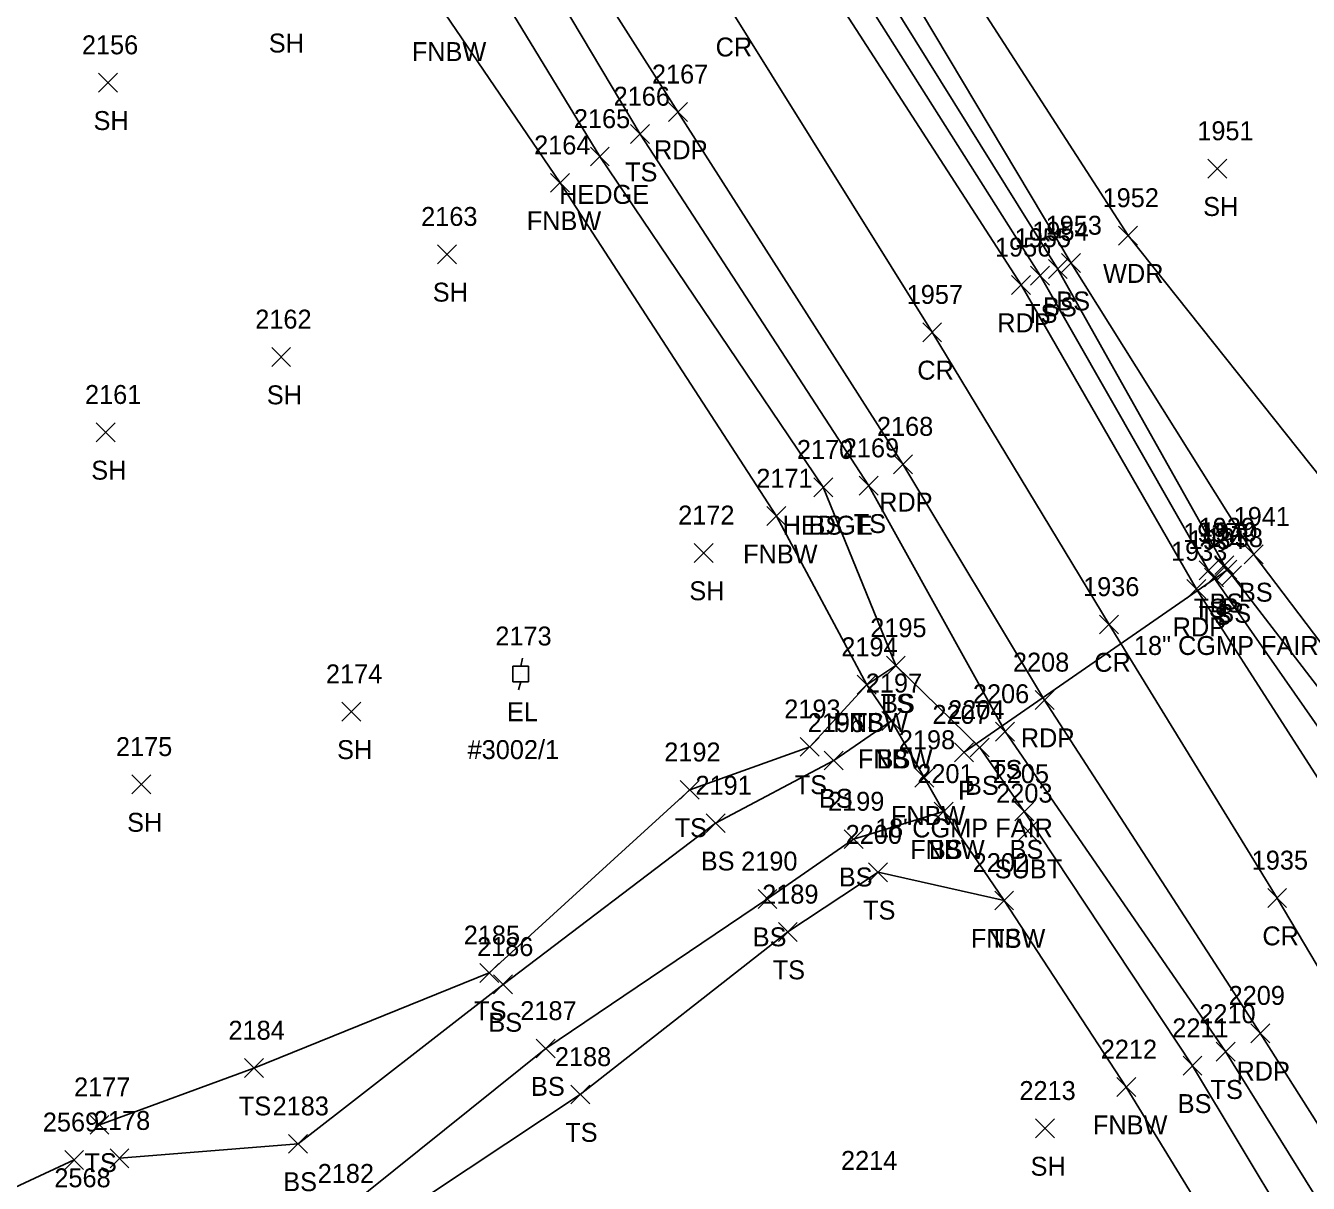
# Model space of a CAD drawing. Extents: x 1443590 to 1445966, y 578314 to 580556.
# Drawn here: x 1444914.1 to 1445049.7, y 579213.2 to 579335.5 of the extents above; entities that cross this region are included whole.
import ezdxf

# ---------------------------------------------------------------- set-up
doc = ezdxf.new("R2010")
doc.units = 0
for name, color, linetype in [('D_A', 7, 'Continuous'), ('D_C', 7, 'Continuous'), ('D_I', 7, 'Continuous'), ('D_TIC', 7, 'Continuous'), ('DCP', 7, 'Continuous'), ('L_A', 7, 'Continuous'), ('L_I', 7, 'Continuous'), ('L_TIC', 7, 'Continuous'), ('LAHR', 7, 'Continuous'), ('LAWA', 7, 'Continuous'), ('LELB', 7, 'Continuous'), ('LFNC', 7, 'Continuous'), ('P_A', 7, 'Continuous'), ('P_I', 7, 'Continuous'), ('P_TIC', 7, 'Continuous'), ('PET', 7, 'Continuous'), ('PRC', 7, 'Continuous'), ('U_A', 7, 'Continuous'), ('U_C', 7, 'Continuous'), ('U_I', 7, 'Continuous'), ('U_TIC', 7, 'Continuous'), ('UEPT', 7, 'Continuous')]:
    doc.layers.add(name, color=color, linetype=linetype)

msp = doc.modelspace()

# ---------------------------------------------------------------- linework, layer by layer
at = {"layer": 'D_TIC'}
for points in [[(1445040.11, 579276.98), (1445042.11, 579278.98)], [(1445042.11, 579276.98), (1445040.11, 579278.98)], [(1445012.28, 579257.7), (1445014.28, 579259.7)], [(1445014.28, 579257.7), (1445012.28, 579259.7)]]:
    msp.add_lwpolyline(points, dxfattribs=at)
at = {"layer": 'DCP'}
msp.add_lwpolyline([(1445041.11, 579277.98), (1445013.28, 579258.7)], dxfattribs=at)
at = {"layer": 'L_TIC'}
for points in [[(1444921.81, 579328.44), (1444923.81, 579330.44)], [(1444923.81, 579328.44), (1444921.81, 579330.44)], [(1444978.05, 579323.01), (1444980.05, 579325.01)], [(1444980.05, 579323.01), (1444978.05, 579325.01)], [(1444973.79, 579320.64), (1444975.79, 579322.64)], [(1444975.79, 579320.64), (1444973.79, 579322.64)], [(1445039.06, 579319.36), (1445041.06, 579321.36)], [(1445041.06, 579319.36), (1445039.06, 579321.36)], [(1444969.59, 579317.86), (1444971.59, 579319.86)], [(1444971.59, 579317.86), (1444969.59, 579319.86)], [(1445029.61, 579312.29), (1445031.61, 579314.29)], [(1445031.61, 579312.29), (1445029.61, 579314.29)], [(1444957.65, 579310.31), (1444959.65, 579312.31)], [(1444959.65, 579310.31), (1444957.65, 579312.31)], [(1445023.59, 579309.38), (1445025.59, 579311.38)], [(1445025.59, 579309.38), (1445023.59, 579311.38)], [(1445020.32, 579308.06), (1445022.32, 579310.06)], [(1445022.32, 579308.06), (1445020.32, 579310.06)], [(1445022.19, 579308.75), (1445024.19, 579310.75)], [(1445024.19, 579308.75), (1445022.19, 579310.75)], [(1444940.12, 579299.46), (1444942.12, 579301.46)], [(1444942.12, 579299.46), (1444940.12, 579301.46)], [(1444921.56, 579291.5), (1444923.56, 579293.5)], [(1444923.56, 579291.5), (1444921.56, 579293.5)], [(1444997.4, 579285.69), (1444999.4, 579287.69)], [(1444999.4, 579285.69), (1444997.4, 579287.69)], [(1444997.4, 579285.69), (1444999.4, 579287.69)], [(1444999.4, 579285.69), (1444997.4, 579287.69)], [(1445002.21, 579285.86), (1445004.21, 579287.86)], [(1445004.21, 579285.86), (1445002.21, 579287.86)], [(1444992.45, 579282.65), (1444994.45, 579284.65)], [(1444994.45, 579282.65), (1444992.45, 579284.65)], [(1444984.76, 579278.76), (1444986.76, 579280.76)], [(1444986.76, 579278.76), (1444984.76, 579280.76)], [(1445042.89, 579278.61), (1445044.89, 579280.61)], [(1445044.89, 579278.61), (1445042.89, 579280.61)], [(1445038.13, 579276.92), (1445040.13, 579278.92)], [(1445040.13, 579276.92), (1445038.13, 579278.92)], [(1445039.78, 579277.47), (1445041.78, 579279.47)], [(1445041.78, 579277.47), (1445039.78, 579279.47)], [(1445038.69, 579276.16), (1445040.69, 579278.16)], [(1445040.69, 579276.16), (1445038.69, 579278.16)], [(1445040.61, 579276.38), (1445042.61, 579278.38)], [(1445042.61, 579276.38), (1445040.61, 579278.38)], [(1445005.07, 579266.86), (1445007.07, 579268.86)], [(1445007.07, 579266.86), (1445005.07, 579268.86)], [(1445005.07, 579266.86), (1445007.07, 579268.86)], [(1445007.07, 579266.86), (1445005.07, 579268.86)], [(1445002, 579264.84), (1445004, 579266.84)], [(1445004, 579264.84), (1445002, 579266.84)], [(1445002, 579264.84), (1445004, 579266.84)], [(1445004, 579264.84), (1445002, 579266.84)], [(1444947.54, 579261.98), (1444949.54, 579263.98)], [(1444949.54, 579261.98), (1444947.54, 579263.98)], [(1445004.6, 579261.01), (1445006.6, 579263.01)], [(1445006.6, 579261.01), (1445004.6, 579263.01)], [(1445004.6, 579261.01), (1445006.6, 579263.01)], [(1445006.6, 579261.01), (1445004.6, 579263.01)], [(1445016.62, 579259.88), (1445018.62, 579261.88)], [(1445018.62, 579259.88), (1445016.62, 579261.88)], [(1444995.98, 579258.27), (1444997.98, 579260.27)], [(1444997.98, 579258.27), (1444995.98, 579260.27)], [(1445013.94, 579258.2), (1445015.94, 579260.2)], [(1445015.94, 579258.2), (1445013.94, 579260.2)], [(1444998.51, 579256.83), (1445000.51, 579258.83)], [(1445000.51, 579256.83), (1444998.51, 579258.83)], [(1444925.35, 579254.3), (1444927.35, 579256.3)], [(1444927.35, 579254.3), (1444925.35, 579256.3)], [(1444983.29, 579253.73), (1444985.29, 579255.73)], [(1444985.29, 579253.73), (1444983.29, 579255.73)], [(1445008.08, 579255.02), (1445010.08, 579257.02)], [(1445010.08, 579255.02), (1445008.08, 579257.02)], [(1445010.12, 579251.44), (1445012.12, 579253.44)], [(1445012.12, 579251.44), (1445010.12, 579253.44)], [(1445010.12, 579251.44), (1445012.12, 579253.44)], [(1445012.12, 579251.44), (1445010.12, 579253.44)], [(1445018.65, 579251.44), (1445020.65, 579253.44)], [(1445020.65, 579251.44), (1445018.65, 579253.44)], [(1444986.02, 579250.21), (1444988.02, 579252.21)], [(1444988.02, 579250.21), (1444986.02, 579252.21)], [(1445000.61, 579248.52), (1445002.61, 579250.52)], [(1445002.61, 579248.52), (1445000.61, 579250.52)], [(1445003.2, 579245.02), (1445005.2, 579247.02)], [(1445005.2, 579245.02), (1445003.2, 579247.02)], [(1444991.51, 579242.2), (1444993.51, 579244.2)], [(1444993.51, 579242.2), (1444991.51, 579244.2)], [(1445016.52, 579242.04), (1445018.52, 579244.04)], [(1445018.52, 579242.04), (1445016.52, 579244.04)], [(1445016.52, 579242.04), (1445018.52, 579244.04)], [(1445018.52, 579242.04), (1445016.52, 579244.04)], [(1444993.66, 579238.71), (1444995.66, 579240.71)], [(1444995.66, 579238.71), (1444993.66, 579240.71)], [(1444962.11, 579234.39), (1444964.11, 579236.39)], [(1444964.11, 579234.39), (1444962.11, 579236.39)], [(1444963.57, 579233.17), (1444965.57, 579235.17)], [(1444965.57, 579233.17), (1444963.57, 579235.17)], [(1444968.08, 579226.4), (1444970.08, 579228.4)], [(1444970.08, 579226.4), (1444968.08, 579228.4)], [(1445039.92, 579226.07), (1445041.92, 579228.07)], [(1445041.92, 579226.07), (1445039.92, 579228.07)], [(1444937.24, 579224.33), (1444939.24, 579226.33)], [(1444939.24, 579224.33), (1444937.24, 579226.33)], [(1445036.42, 579224.58), (1445038.42, 579226.58)], [(1445038.42, 579224.58), (1445036.42, 579226.58)], [(1444971.73, 579221.54), (1444973.73, 579223.54)], [(1444973.73, 579221.54), (1444971.73, 579223.54)], [(1445029.43, 579222.33), (1445031.43, 579224.33)], [(1445031.43, 579222.33), (1445029.43, 579224.33)], [(1444920.92, 579218.34), (1444922.92, 579220.34)], [(1444922.92, 579218.34), (1444920.92, 579220.34)], [(1445020.83, 579217.96), (1445022.83, 579219.96)], [(1445022.83, 579217.96), (1445020.83, 579219.96)], [(1444941.9, 579216.33), (1444943.9, 579218.33)], [(1444943.9, 579216.33), (1444941.9, 579218.33)], [(1444918.24, 579214.63), (1444920.24, 579216.63)], [(1444920.24, 579214.63), (1444918.24, 579216.63)], [(1444923.03, 579214.8), (1444925.03, 579216.8)], [(1444925.03, 579214.8), (1444923.03, 579216.8)]]:
    msp.add_lwpolyline(points, dxfattribs=at)
at = {"layer": 'LAHR'}
msp.add_lwpolyline([(1444864.79, 579494.03), (1444884.87, 579461.17), (1444906.03, 579429.64), (1444929.84, 579393.46), (1444956.06, 579352.42), (1444974.79, 579321.64), (1444998.4, 579286.69)], dxfattribs=at)
at = {"layer": 'LAWA'}
msp.add_lwpolyline([(1445116.41, 579282.36), (1445091.57, 579273.6), (1445068.08, 579261.13), (1445063.97, 579265.77), (1445052.44, 579285.91), (1445030.61, 579313.29), (1445007.29, 579349.44), (1444981.88, 579393.33), (1444958.1, 579429.17), (1444930.43, 579469.34), (1444907.58, 579503.94), (1444877.79, 579540.6), (1444853.64, 579577.69), (1444828.42, 579618.05), (1444811.24, 579649.86), (1444793.14, 579680.39), (1444780.3, 579709.09)], dxfattribs=at)
at = {"layer": 'LELB'}
for points in [[(1445120.88, 579277.2), (1445094.09, 579267.75), (1445069.76, 579257.75), (1445059.62, 579258.9), (1445056.87, 579257.54), (1445041.61, 579277.38), (1445040.78, 579278.47), (1445023.19, 579309.75), (1445001.25, 579344.99), (1444974.42, 579387.92), (1444950.97, 579424.44), (1444924.55, 579463.55), (1444901.05, 579499.1), (1444872.7, 579536.92), (1444847.2, 579572.49), (1444820.99, 579613.47), (1444802.94, 579645.55), (1444786.24, 579676.71), (1444770.75, 579705.77)], [(1445059.62, 579258.9), (1445043.89, 579279.61), (1445024.59, 579310.38), (1445003.03, 579346.49), (1444976.79, 579389.55), (1444952.41, 579425.12), (1444926.34, 579464.68), (1444902.15, 579500.76), (1444874.51, 579538.34), (1444849.34, 579574.14), (1444822.42, 579614.33), (1444804.62, 579646.57), (1444787.75, 579677.64), (1444772.75, 579706.54)], [(1445120.75, 579274.75), (1445095.98, 579262.15), (1445072.07, 579253.49), (1445056.72, 579252.73), (1445039.69, 579277.16), (1445039.13, 579277.92), (1445021.32, 579309.06), (1444999.24, 579343.98), (1444972.54, 579386.39), (1444948.75, 579423.47), (1444922.09, 579461.69), (1444897.81, 579497.23), (1444870.77, 579536.13), (1444845.96, 579571.78), (1444819.96, 579613.15), (1444802.08, 579645.41), (1444784.76, 579676.08), (1444769.89, 579705.02)], [(1444960.57, 579355.06), (1444979.05, 579324.01), (1445003.21, 579286.86), (1445017.62, 579260.88), (1445040.92, 579227.07), (1445056.02, 579202.79), (1445077.14, 579169.23), (1445087.88, 579152.95), (1445100.68, 579131.75), (1445100.63, 579124.41), (1445093.66, 579121.61), (1445094.66, 579118.69), (1445096.17, 579112.31), (1445078.21, 579111.11), (1445047.27, 579111.15), (1445003.8, 579115.46), (1444971.29, 579119.24), (1444952.39, 579122.15), (1444898.08, 579130.8), (1444861.08, 579136.75), (1444840.2, 579139.58), (1444804.45, 579145.03), (1444761.25, 579150.91)], [(1444998.4, 579286.69), (1445006.07, 579267.86), (1445014.94, 579259.2), (1445019.65, 579252.44), (1445037.42, 579225.58), (1445052.31, 579200.79), (1445074.22, 579167.6), (1445083.91, 579150.21), (1445100.63, 579124.41)], [(1444921.92, 579219.34), (1444938.24, 579225.33), (1444963.11, 579235.39), (1444984.29, 579254.73), (1444996.98, 579259.27), (1445003, 579265.84), (1445006.07, 579267.86)], [(1444924.03, 579215.8), (1444942.9, 579217.33), (1444964.57, 579234.17), (1444987.02, 579251.21), (1444999.51, 579257.83), (1445005.6, 579262.01)], [(1444928.04, 579206.43), (1444947.67, 579210.2), (1444969.08, 579227.4), (1444992.51, 579243.2), (1445001.61, 579249.52), (1445011.12, 579252.44)], [(1444930.6, 579201.16), (1444949.06, 579206.82), (1444972.73, 579222.54), (1444994.66, 579239.71), (1445004.2, 579246.02), (1445017.52, 579243.04)], [(1444919.24, 579215.63), (1444903.05, 579208.11), (1444885.02, 579194.5), (1444865.75, 579185.31), (1444848.32, 579178.64), (1444837.14, 579166.25), (1444806.08, 579168.28), (1444761.27, 579170.06), (1444728.49, 579174.89), (1444695.59, 579190.16), (1444696.54, 579181.03), (1444600.23, 579193.23), (1444579.91, 579197.07)]]:
    msp.add_lwpolyline(points, dxfattribs=at)
at = {"layer": 'LFNC'}
msp.add_lwpolyline([(1444958.45, 579336.73), (1444970.59, 579318.86), (1444993.45, 579283.65), (1445003, 579265.84), (1445005.6, 579262.01), (1445009.08, 579256.02), (1445011.12, 579252.44), (1445017.52, 579243.04), (1445030.43, 579223.33), (1445046.2, 579197.57), (1445067.06, 579164.31), (1445076.05, 579150.8), (1445061.88, 579136.87), (1445051.99, 579130.81), (1445025.41, 579131.6), (1445002.72, 579133.11)], dxfattribs=at)
at = {"layer": 'P_TIC'}
for points in [[(1444982.04, 579325.35), (1444984.04, 579327.35)], [(1444984.04, 579325.35), (1444982.04, 579327.35)], [(1445018.3, 579307.07), (1445020.3, 579309.07)], [(1445020.3, 579307.07), (1445018.3, 579309.07)], [(1445008.91, 579302.07), (1445010.91, 579304.07)], [(1445010.91, 579302.07), (1445008.91, 579304.07)], [(1445005.82, 579288.13), (1445007.82, 579290.13)], [(1445007.82, 579288.13), (1445005.82, 579290.13)], [(1445036.84, 579274.94), (1445038.84, 579276.94)], [(1445038.84, 579274.94), (1445036.84, 579276.94)], [(1445027.61, 579271.2), (1445029.61, 579273.2)], [(1445029.61, 579271.2), (1445027.61, 579273.2)], [(1445020.79, 579263.22), (1445022.79, 579265.22)], [(1445022.79, 579263.22), (1445020.79, 579265.22)], [(1445045.37, 579242.3), (1445047.37, 579244.3)], [(1445047.37, 579242.3), (1445045.37, 579244.3)], [(1445043.58, 579228.01), (1445045.58, 579230.01)], [(1445045.58, 579228.01), (1445043.58, 579230.01)]]:
    msp.add_lwpolyline(points, dxfattribs=at)
at = {"layer": 'PET'}
for points in [[(1445187.64, 579104.95), (1445149.35, 579115.57), (1445134.36, 579130.22), (1445115.96, 579155.83), (1445098.76, 579182.02), (1445071.93, 579223.13), (1445057.22, 579245.8), (1445037.84, 579275.94), (1445019.3, 579308.07), (1444997.05, 579342.56), (1444969.98, 579385.25), (1444946.15, 579421.86), (1444919.7, 579460.87), (1444895.29, 579496.39), (1444868.39, 579534.19), (1444844.21, 579570.94), (1444818.42, 579612.05), (1444800.46, 579644.42), (1444783.19, 579675.42), (1444768.08, 579703.75)], [(1444749.57, 579692.99), (1444767.18, 579659.68), (1444778.42, 579640.07), (1444792.21, 579615.83), (1444803.11, 579597.28), (1444822.86, 579565.6), (1444843.8, 579533.42), (1444869.08, 579496.25), (1444890.19, 579465.65), (1444913.09, 579433.16), (1444937.14, 579397.54), (1444963.6, 579356.94), (1444983.04, 579326.35), (1445006.82, 579289.13), (1445021.79, 579264.22), (1445044.58, 579229.01), (1445059.66, 579205.24), (1445081.95, 579172.07), (1445091.01, 579154.93), (1445104.63, 579132.07), (1445107.77, 579117.84), (1445102.26, 579109.52), (1445094.76, 579101.93)]]:
    msp.add_lwpolyline(points, dxfattribs=at)
at = {"layer": 'PRC'}
msp.add_lwpolyline([(1445134.69, 579101.81), (1445120.96, 579124.75), (1445105.7, 579149.31), (1445088.61, 579176.47), (1445062.61, 579215.94), (1445046.37, 579243.3), (1445028.61, 579272.2), (1445009.91, 579303.07), (1444988.59, 579337.21), (1444961.47, 579379.67), (1444937.03, 579417.04), (1444911.02, 579455.05), (1444885.8, 579491.61), (1444860.37, 579528.28), (1444835.41, 579566.04), (1444809.93, 579606.59), (1444790.8, 579639.57), (1444773.48, 579670.26), (1444758.9, 579698.36)], dxfattribs=at)
at = {"layer": 'U_TIC'}
for points in [[(1445019.02, 579249.38), (1445021.02, 579251.38)], [(1445021.02, 579249.38), (1445019.02, 579251.38)]]:
    msp.add_lwpolyline(points, dxfattribs=at)
at = {"layer": 'UEPT'}
for p, q in [((1444966.61, 579268.64), (1444966.44, 579267.81)), ((1444965.61, 579266.14), (1444965.61, 579267.81)), ((1444965.61, 579267.81), (1444967.27, 579267.81)), ((1444966.44, 579266.98), (1444966.44, 579266.98)), ((1444967.27, 579267.81), (1444967.27, 579266.14)), ((1444967.27, 579266.14), (1444965.61, 579266.14)), ((1444966.19, 579265.31), (1444966.44, 579266.14))]:
    msp.add_line(p, q, dxfattribs=at)

# ---------------------------------------------------------------- texts
at = {"layer": 'D_A'}
for p in [(1445040.49, 579272.98), (1445012.65, 579253.7)]:
    msp.add_text('P', height=2, dxfattribs=at).set_placement(p)
at = {"layer": 'D_C'}
for s, p in [('18" CGMP FAIR', (1445031.23, 579268.98)), ('18"CGMP FAIR', (1445003.88, 579249.7))]:
    msp.add_text(s, height=2, dxfattribs=at).set_placement(p)
at = {"layer": 'D_I'}
for s, p in [('1940', (1445038.33, 579280.98)), ('2207', (1445009.94, 579261.7))]:
    msp.add_text(s, height=2, dxfattribs=at).set_placement(p)
at = {"layer": 'L_A'}
for s, p in [('SH', (1444939.81, 579332.63)), ('FNBW', (1444954.92, 579331.73)), ('SH', (1444921.29, 579324.44)), ('TS', (1444977.46, 579319.01)), ('HEDGE', (1444970.49, 579316.64)), ('SH', (1445038.55, 579315.36)), ('FNBW', (1444967.07, 579313.86)), ('WDR', (1445027.97, 579308.29)), ('SH', (1444957.14, 579306.31)), ('BS', (1445023.03, 579305.38)), ('TS', (1445019.73, 579304.06)), ('BS', (1445021.63, 579304.75)), ('SH', (1444939.6, 579295.46)), ('SH', (1444921.05, 579287.5)), ('HEDGE', (1444994.11, 579281.69)), ('BS', (1444996.85, 579281.69)), ('TS', (1445001.62, 579281.86)), ('FNBW', (1444989.93, 579278.65)), ('SH', (1444984.25, 579274.76)), ('BS', (1445042.33, 579274.61)), ('TS', (1445037.54, 579272.92)), ('BS', (1445039.22, 579273.47)), ('TS', (1445038.09, 579272.16)), ('BS', (1445040.05, 579272.38)), ('TS', (1445004.48, 579262.86)), ('BS', (1445004.51, 579262.86)), ('FNBW', (1444999.47, 579260.84)), ('TS', (1445001.41, 579260.84)), ('SH', (1444947.03, 579257.98)), ('FNBW', (1445002.07, 579257.01)), ('BS', (1445004.04, 579257.01)), ('TS', (1445016.03, 579255.88)), ('TS', (1444995.39, 579254.27)), ('BS', (1445013.38, 579254.2)), ('BS', (1444997.95, 579252.83)), ('FNBW', (1445005.55, 579251.02)), ('SH', (1444924.84, 579250.3)), ('TS', (1444982.7, 579249.73)), ('FNBW', (1445007.59, 579247.44)), ('BS', (1445009.56, 579247.44)), ('BS', (1445018.09, 579247.44)), ('BS', (1444985.46, 579246.21)), ('BS', (1445000.05, 579244.52)), ('TS', (1445002.61, 579241.02)), ('BS', (1444990.95, 579238.2)), ('FNBW', (1445014, 579238.04)), ('TS', (1445015.93, 579238.04)), ('TS', (1444993.06, 579234.71)), ('TS', (1444961.52, 579230.39)), ('BS', (1444963.01, 579229.17)), ('BS', (1444967.52, 579222.4)), ('TS', (1445039.33, 579222.07)), ('TS', (1444936.65, 579220.33)), ('BS', (1445035.86, 579220.58)), ('TS', (1444971.14, 579217.54)), ('FNBW', (1445026.9, 579218.33)), ('TS', (1444920.33, 579214.34)), ('SH', (1445020.31, 579213.96)), ('BS', (1444941.34, 579212.33))]:
    msp.add_text(s, height=2, dxfattribs=at).set_placement(p)
at = {"layer": 'L_I'}
for s, p in [('2156', (1444920.06, 579332.44)), ('2166', (1444976.25, 579327.01)), ('2165', (1444972.05, 579324.64)), ('1951', (1445037.93, 579323.36)), ('2164', (1444967.85, 579321.86)), ('1952', (1445027.92, 579316.29)), ('2163', (1444955.91, 579314.31)), ('1953', (1445021.9, 579313.38)), ('1955', (1445018.63, 579312.06)), ('1954', (1445020.5, 579312.75)), ('2162', (1444938.38, 579303.46)), ('2161', (1444920.39, 579295.5)), ('2170', (1444995.62, 579289.69)), ('2170', (1444995.62, 579289.69)), ('2169', (1445000.47, 579289.86)), ('2171', (1444991.33, 579286.65)), ('2172', (1444983.07, 579282.76)), ('1941', (1445041.77, 579282.61)), ('1937', (1445036.44, 579280.92)), ('1939', (1445038.08, 579281.47)), ('1934', (1445036.99, 579280.16)), ('1938', (1445038.92, 579280.38)), ('2195', (1445003.37, 579270.86)), ('2195', (1445003.37, 579270.86)), ('2194', (1445000.31, 579268.84)), ('2194', (1445000.31, 579268.84)), ('2174', (1444945.85, 579265.98)), ('2197', (1445002.9, 579265.01)), ('2197', (1445002.9, 579265.01)), ('2206', (1445014.22, 579263.88)), ('2193', (1444994.28, 579262.27)), ('2204', (1445011.6, 579262.2)), ('2196', (1444996.76, 579260.83)), ('2175', (1444923.66, 579258.3)), ('2192', (1444981.6, 579257.73)), ('2198', (1445006.39, 579259.02)), ('2201', (1445008.34, 579255.44)), ('2201', (1445008.34, 579255.44)), ('2205', (1445016.31, 579255.44)), ('2191', (1444984.9, 579254.21)), ('2199', (1444998.91, 579252.52)), ('2200', (1445000.77, 579249.02)), ('2190', (1444989.73, 579246.2)), ('2202', (1445014.19, 579246.04)), ('2202', (1445014.19, 579246.04)), ('2189', (1444991.95, 579242.71)), ('2185', (1444960.41, 579238.39)), ('2186', (1444961.82, 579237.17)), ('2187', (1444966.39, 579230.4)), ('2210', (1445038.14, 579230.07)), ('2184', (1444935.55, 579228.33)), ('2211', (1445035.29, 579228.58)), ('2188', (1444970.04, 579225.54)), ('2212', (1445027.73, 579226.33)), ('2177', (1444919.23, 579222.34)), ('2213', (1445019.13, 579221.96)), ('2183', (1444940.21, 579220.33)), ('2569', (1444915.93, 579218.63)), ('2178', (1444921.33, 579218.8)), ('2214', (1445000.28, 579214.58)), ('2182', (1444944.98, 579213.2)), ('2568', (1444917.15, 579212.74))]:
    msp.add_text(s, height=2, dxfattribs=at).set_placement(p)
at = {"layer": 'P_A'}
for s, p in [('CR', (1444987.03, 579332.21)), ('RDP', (1444980.52, 579321.35)), ('RDP', (1445016.79, 579303.07)), ('CR', (1445008.34, 579298.07)), ('RDP', (1445004.31, 579284.13)), ('RDP', (1445035.33, 579270.94)), ('CR', (1445027.04, 579267.2)), ('RDP', (1445019.28, 579259.22)), ('CR', (1445044.81, 579238.3)), ('RDP', (1445042.07, 579224.01))]:
    msp.add_text(s, height=2, dxfattribs=at).set_placement(p)
at = {"layer": 'P_I'}
for s, p in [('2167', (1444980.3, 579329.35)), ('1956', (1445016.55, 579311.07)), ('1957', (1445007.22, 579306.07)), ('2168', (1445004.08, 579292.13)), ('1933', (1445035.15, 579278.94)), ('1936', (1445025.86, 579275.2)), ('2208', (1445018.45, 579267.22)), ('1935', (1445043.68, 579246.3)), ('2209', (1445041.24, 579232.01))]:
    msp.add_text(s, height=2, dxfattribs=at).set_placement(p)
at = {"layer": 'U_A'}
for s, p in [('EL', (1444964.98, 579261.98)), ('SUBT', (1445016.52, 579245.38))]:
    msp.add_text(s, height=2, dxfattribs=at).set_placement(p)
at = {"layer": 'U_C'}
msp.add_text('#3002/1', height=2, dxfattribs=at).set_placement((1444960.82, 579257.98))
at = {"layer": 'U_I'}
for s, p in [('2173', (1444963.75, 579269.98)), ('2203', (1445016.68, 579253.38))]:
    msp.add_text(s, height=2, dxfattribs=at).set_placement(p)

doc.saveas('drawing.dxf')
